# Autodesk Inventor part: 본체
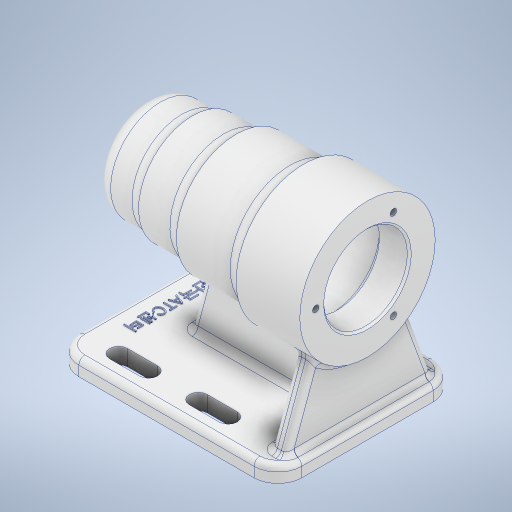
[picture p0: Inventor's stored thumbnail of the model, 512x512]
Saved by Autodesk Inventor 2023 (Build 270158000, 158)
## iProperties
Created: 2022-07
Part Number: 본체
Material: 알루미늄 6061
Document SubType Name: Modeling
Designer: owner
Density: 2.7 g/cm^3
Appearance: 알루미늄 - 평지
Mass: 702.592 g
Surface Area: 702.258 cm^2
Volume: 260.219 cm^3
Author: owner
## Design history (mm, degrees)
sketch "스케치1"
  geometry: L1 (-56, 0)-(56, 0); L2 (-56, 0)-(-56, 17); L3 (-48, 25)-(-32, 25); L4 (-32, 25)-(-32, 27); L5 (-32, 27)-(-10, 27); L6 (-10, 27)-(-10, 30); L7 (-10, 30)-(24, 30); L8 (24, 30)-(24, 34); L9 (24, 34)-(56, 34); L10 (56, 34)-(56, 0); A1 r 8 centre (-48, 17) between (-48, 25) and (-56, 17); 3 further points
  constraints: 20 end point, 8 perpendicular, 2 point on circle, 2 point on line, 2 tangent, 1 centre point, 1 coincident, 1 horizontal, 1 midpoint, 1 vertical
  dimensions: "d1" = 25 distance of L1.start point (-56, 25); "d2" = 24 distance of point (-56, 25) L3.end; "d3" = 2 distance of L3.end L4.end; "d4" = 22 distance of L4.end L5.end; "d5" = 3 distance of L5.end L6.end; "d6" = 34 distance of L6.end L7.end; "d7" = 4 distance of L7.end L8.end; "d8" = 32 distance of L8.end L9.end; "d9" = 8 radius of A1
revolve "회전1" sketch "스케치1" stored, may be unused: angle "d10" = 90 deg
fillet "모깎기1" dims "d11" = 8
sketch "스케치2"
  geometry: L1 (-56, -17)-(-56, 17) reference; L2 (-56, 0)-(56, 0); L3 (56, -34)-(56, 34) reference; L4 (56, 0)-(56, 21); L5 (56, 21)-(41, 21); L6 (41, 21)-(41, 21); L7 (38, 24)-(-10, 24); L8 (-13, 21)-(-13, 21); L9 (-13, 21)-(-24.7, 21); L10 (-25, 20.7)-(-25, 17.5); L11 (-25, 17.5)-(-42.7, 17.5); L12 (-37.292, -25)-(-37.292, 25) reference; L13 (-43, 17.2)-(-43, 16); L14 (-43, 16)-(-46.7, 16); L15 (-48, -25)-(-48, 25) reference; L16 (-47, 15.7)-(-47, 10.5); L17 (-47, 10.5)-(-47, 10.5); L18 (-50, 7.5)-(-50, 0); A1 r 0.3 centre (-46.7, 15.7) between (-46.7, 16) and (-47, 15.7); A2 r 0.3 centre (-42.7, 17.2) between (-42.7, 17.5) and (-43, 17.2); A3 r 0.3 centre (-24.7, 20.7) between (-24.7, 21) and (-25, 20.7); A4 r 3 centre (-47, 7.5) between (-47, 10.5) and (-50, 7.5); A5 r 3 centre (-10, 21) between (-10, 24) and (-13, 21); A6 r 3 centre (38, 21) between (41, 21) and (38, 24); 7 further points
  constraints: 28 end point, 12 point on circle, 12 tangent, 10 perpendicular, 10 point on line, 6 centre point, 2 equal radius, 2 midpoint, 1 horizontal
  dimensions: "d12" = 42 diameter of L5 L2; "d13" = 48 diameter of L7 L2; "d14" = 15 distance between parallel lines of L3 L6; "d15" = 54 distance between parallel lines of L8 L6; "d16" = 18 distance of L10.end point (-43, 17.5); "d17" = 12 distance of L8.end point (-25, 21); "d18" = 35 diameter of L11 L2; "d19" = 32 diameter of L14 L2; "d20" = 21 diameter of L17 L2; "d21" = 3 distance between parallel lines of L16 L18; "d22" = 4 distance between parallel lines of L13 L16; "d23" = 0.3 radius of A1 (derived); "d24" = 3 radius of A4; "d25" = 3 radius of A5 (derived); "d101" = 3 radius of A6 (derived)
revolve "회전2" sketch "스케치2" stored, may be unused: angle "d26" = 90 deg
chamfer "모따기1" distance "d27" = 1; stored, may be unused: second distance "d28" = 2, angle "d29" = 45 deg
sketch "스케치3" dims "d37" = 52
  geometry: 5 further points
  constraints: 1 coincident, 1 horizontal alignment, 7 other
  dimensions: "d40" = 360 deg dimension on point (0, 0) point (13, 22.517) (derived)
hole "구멍1" sketch "스케치3" at (13, 22.517), (-26, 0), (13, -22.517) diameter "d30" = 3.242; stored, may be unused: countersink angle "d34" = 90 deg, drill point angle "d36" = 118 deg; dims "d31" = 8, "d32" = 4, "d33" = 2, "d35" = 11
node "작업 평면1"
sketch "스케치4"
  geometry: L1 (-44, 45)-(44, 45); L2 (56, 33)-(56, -33); L3 (44, -45)-(-44, -45); L4 (-56, -33)-(-56, 33); L5 (-56, 45)-(56, -45); L6 (56, 45)-(-56, -45); A1 r 12 centre (44, -33) between (44, -45) and (56, -33); A2 r 12 centre (-44, -33) between (-56, -33) and (-44, -45); A3 r 12 centre (-44, 33) between (-44, 45) and (-56, 33); A4 r 12 centre (44, 33) between (56, 33) and (44, 45); 1 further point
  constraints: 12 end point, 8 point on circle, 8 point on line, 8 tangent, 4 centre point, 3 equal radius, 2 midpoint, 2 parallel, 1 horizontal, 1 perpendicular
  dimensions: "d43" = 90 distance of L6.start L5.end; "d44" = 112 distance of L5.end L6.end; "d45" = 12 radius of A1
extrude "돌출1" join sketch "스케치4" distance "d46" = 8; taper "d47" = 0 deg
fillet "모깎기2" dims "d48" = 3
sketch "스케치5"
  geometry: L1 (-36, 33)-(-21, 33); L2 (-36, 28.5)-(-21, 28.5); L3 (-21, 37.5)-(-36, 37.5); L4 (4, 33)-(19, 33); L5 (4, 28.5)-(19, 28.5); L6 (19, 37.5)-(4, 37.5); L7 (-56, 33)-(-56, -33) reference; L8 (-56, 33)-(-56, -33) reference; L9 (-56, 0)-(56, 0); L10 (56, -33)-(56, 33) reference; L11 (-21, -37.5)-(-36, -37.5); L12 (-36, -28.5)-(-21, -28.5); L13 (19, -37.5)-(4, -37.5); L14 (4, -28.5)-(19, -28.5); A1 r 4.5 centre (-36, 33) between (-36, 37.5) and (-36, 28.5); A2 r 4.5 centre (-21, 33) between (-21, 28.5) and (-21, 37.5); A3 r 4.5 centre (4, 33) between (4, 37.5) and (4, 28.5); A4 r 4.5 centre (19, 33) between (19, 28.5) and (19, 37.5); A5 r 4.5 centre (-36, -33) between (-36, -28.5) and (-36, -37.5); A6 r 4.5 centre (-21, -33) between (-21, -37.5) and (-21, -28.5); A7 r 4.5 centre (4, -33) between (4, -28.5) and (4, -37.5); A8 r 4.5 centre (19, -33) between (19, -37.5) and (19, -28.5); 3 further points
  constraints: 26 end point, 16 point on circle, 12 symmetric about line, 8 centre point, 8 tangent, 4 midpoint, 2 parallel, 2 point on line, 1 horizontal, 1 horizontal alignment, 4 other
  dimensions: "d49" = 15 distance of L1.start L1.end; "d50" = 9 diameter of A2; "d51" = 15 distance of L4.start L4.end; "d52" = 9 diameter of A4; "d57" = 20 distance from line of L7 L1.start; "d58" = 25 distance of L4.start L1.end; "d62" = 66 diameter of L1.start L9
extrude "돌출2" cut sketch "스케치5" extent not by distance; stored distance "d63" = 0; taper "d64" = 0 deg
sketch "스케치8"
  geometry: L1 (-44, -62)-(44, -62) reference; L2 (-29, -62)-(-19.232, -25.544); L3 (-29, -62)-(8.742, -62); L4 (-19.232, -25.544)-(48, -25.544); L5 (56, -34)-(56, 34) reference; L6 (48, -25.544)-(48, -62); L7 (56, -70)-(56, -65) reference; L8 (44, -70)-(-44, -70) reference; L9 (-29, -62)-(48, -62); 2 further points
  constraints: 10 end point, 1 collinear, 1 equal length, 1 horizontal, 1 perpendicular, 1 point on line, 1 vertical
  dimensions: "d77" = 75 deg angle of L3 L2; "d79" = 8 distance between parallel lines of L7 L6; "d80" = 77 distance from line of L2.start L6; "d81" = 44.45645 distance between parallel lines of L8 L4
extrude "돌출3" join sketch "스케치8" stored distance "d82" = 8; taper "d83" = 0 deg
sketch "스케치9"
  geometry: L1 (-33.5, 0)-(-24.5, 0) reference; L2 (-33, 0)-(-19.075, 38.257); L3 (-33, 0)-(7.713, 0); L4 (-19.075, 38.257)-(27.075, 38.257); L5 (27.075, 38.257)-(41, 0); L6 (37, 0)-(46, 0) reference; L7 (27.075, 38.257)-(67.788, 38.257); L8 (-41, -8)-(-41, -3) reference; L9 (49, -8)-(49, -3) reference; L10 (37, -8)-(-29, -8) reference; L11 (-29, 0)-(37, 0) reference; L12 (32.5, 0)-(41.5, 0) reference; 1 further point
  constraints: 10 end point, 2 equal length, 2 horizontal, 2 point on line, 1 parallel
  dimensions: "d84" = 70 deg angle of L3 L2; "d85" = 70 deg angle of L5 L7; "d86" = 8 distance from line of L8 L2.start; "d87" = 8 distance from line of L9 L5.end; "d89" = 46.25738 distance between parallel lines of L10 L4
extrude "돌출4" join sketch "스케치9" stored distance "d90" = 8; taper "d91" = 0 deg
fillet "모깎기3" dims "d92" = 3
fillet "모깎기4" dims "d93" = 3
fillet "모깎기5" dims "d94" = 3
fillet "모깎기6" dims "d95" = 3
fillet "모깎기7" dims "d96" = 3
fillet "모깎기8" dims "d97" = 3
sketch "스케치10"
  geometry: L1 (-56, 33)-(-56, -33) reference; 2 further points
  constraints: 1 horizontal alignment, 1 other
  dimensions: "d98" = 12 distance from line of L1 point (-44, 0)
feature "엠보싱1" sketch "스케치10" dims "d1" = 25, "d2" = 24, "d3" = 2, "d4" = 22, "d5" = 3, "d6" = 34, "d7" = 4, "d8" = 32, "d9" = 8, "d12" = 42, "d13" = 48, "d14" = 15, "d15" = 54, "d16" = 18, "d17" = 12, "d18" = 35, "d19" = 32, "d20" = 21, "d21" = 3, "d22" = 4, "d23" = 0.3 (derived), "d24" = 3, "d25" = 3 (derived), "d99" = 0.5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
node "솔리드1"
feature "A9D066F2-1C7D-4E18-AEED-F7BC21143FA4" dims "d30" = 3.242, "d31" = 8, "d32" = 4, "d33" = 2, "d34" = 90 deg, "d35" = 11, "d36" = 118 deg
